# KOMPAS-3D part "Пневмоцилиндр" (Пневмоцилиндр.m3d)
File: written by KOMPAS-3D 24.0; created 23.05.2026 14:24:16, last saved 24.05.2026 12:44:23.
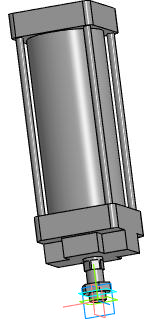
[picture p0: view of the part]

Document properties: Автор: R2D2; Полное имя файла: E:\Работа\Зайцев\GVKR1331E-1W-Fb-2P Задвижка шиберная DN.ru Ду50-300 Ру16-10-6\исходные материалы\DN200\Пневмоцилиндр.m3d

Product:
- Part/product: Пневмоцилиндр
    Масса: 44.90287

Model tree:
1. Эскиз:1
2. Элемент выдавливания:1
3. Смещенная плоскость:1
4. Эскиз:2
5. Элемент выдавливания:2
6. Эскиз:3  (with: Грань.Элемент выдавливания:1)
7. Элемент выдавливания:3
     Расстояние 1 = 3.29033e-05
8. Эскиз:4  (with: Грань.Элемент выдавливания:3)
9. Элемент выдавливания:4  (with: Грань.Элемент выдавливания:3)
     Расстояние 2 = 15; Смещение 2 = 5
10. Эскиз:5  (with: Грань.Элемент выдавливания:3)
11. Элемент выдавливания:5
     Расстояние 1 = 141320
12. Эскиз:6  (with: Грань.Элемент выдавливания:5)
13. Элемент выдавливания:6
14. Эскиз:7  (with: Грань.Элемент выдавливания:6)
15. Элемент выдавливания:7
16. Эскиз:8  (with: Грань.Элемент выдавливания:7, Ребро.Элемент выдавливания:6)
17. Элемент выдавливания:8
18. Эскиз:9  (with: Грань.Элемент выдавливания:6, Вершина.Элемент выдавливания:8)
19. Элемент выдавливания:9  (with: Грань.Элемент выдавливания:8)
     Расстояние 1 = 294
20. Массив по концентрической сетке:1  (with: Элемент выдавливания:9, Эскиз:9)  (4 pattern instances)
     Шаг 2 = 360
21. Скругление:1  (with: Ребро.Элемент выдавливания:6, Ребро.Элемент выдавливания:8)
     Радиус = 10
22. Эскиз:10  (with: Грань.Элемент выдавливания:5, Ребро.Элемент выдавливания:6, Ребро.Элемент выдавливания:8)
23. Элемент выдавливания:10
24. Эскиз:11  (with: Грань.Элемент выдавливания:5, Ребро.Элемент выдавливания:10)
25. Элемент выдавливания:11
26. Эскиз:12  (with: Ребро.Элемент выдавливания:6, Ребро.Элемент выдавливания:5)
27. Элемент выдавливания:12

Expressions: k/2; c-2*g+x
